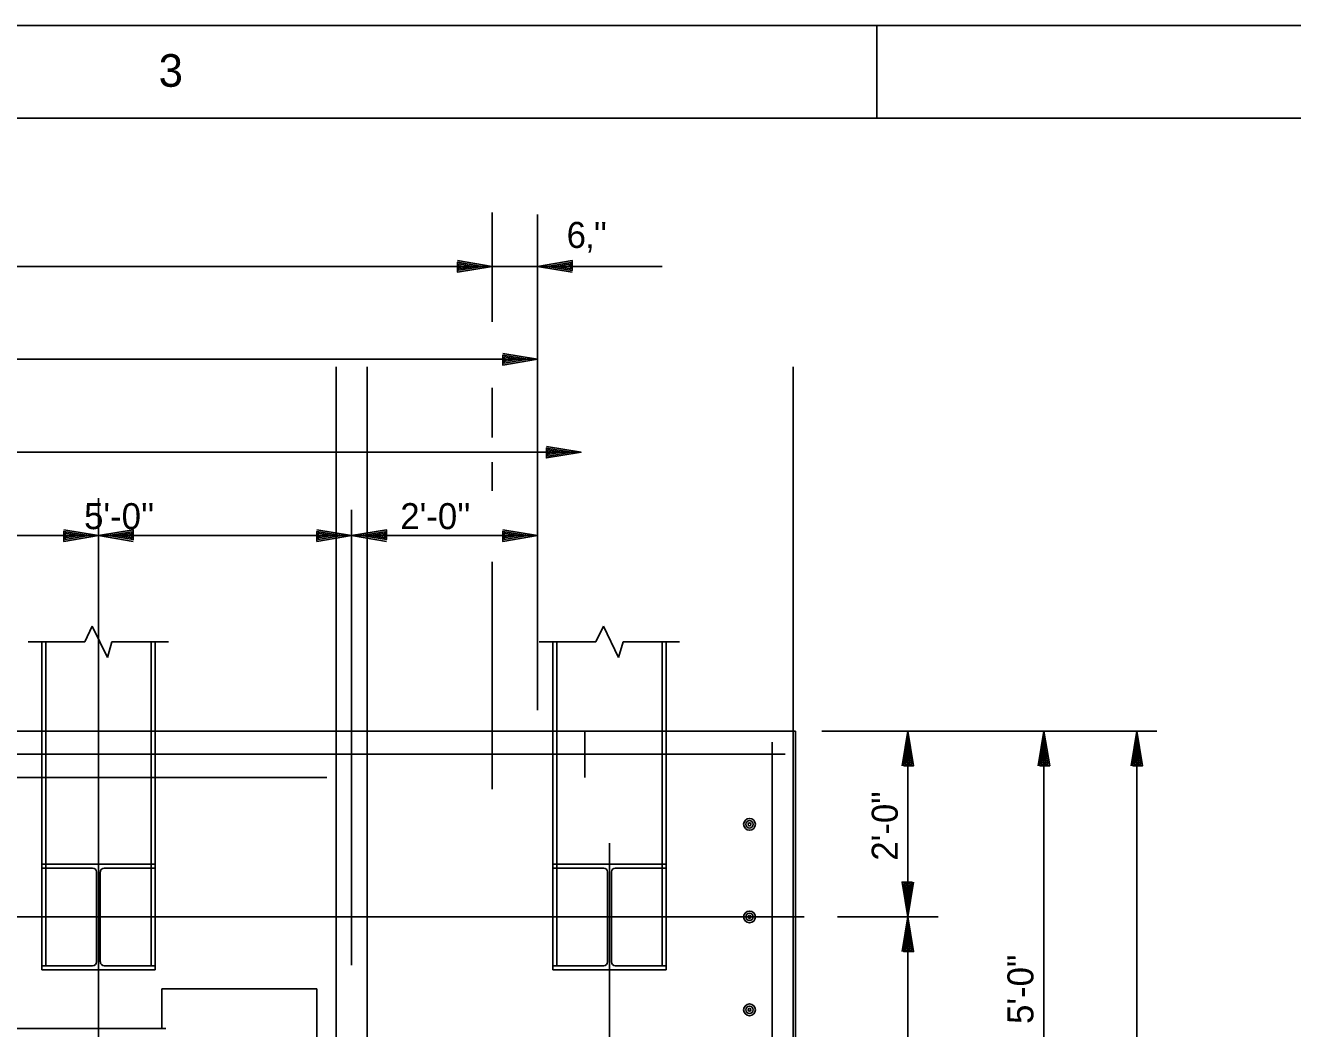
# Model space of a CAD drawing. Extents: x -11983 to -11903, y -13969.5 to -13913.5.
# Drawn here: x -11943.67 to -11930.04, y -13924.28 to -13913.48 of the extents above; entities that cross this region are included whole.
import ezdxf

# ---------------------------------------------------------------- set-up
doc = ezdxf.new("R2010")
doc.units = 0
for name, color, linetype in [('Level 1', 7, 'Continuous'), ('Level 2', 7, 'Continuous'), ('Level 22', 7, 'Continuous'), ('Level 25', 7, 'Continuous'), ('Level 3', 7, 'Continuous'), ('Level 50', 7, 'Continuous'), ('Level 6', 7, 'Continuous')]:
    doc.layers.add(name, color=color, linetype=linetype)

msp = doc.modelspace()

# ---------------------------------------------------------------- linework, layer by layer
at = {"layer": 'Level 1'}
msp.add_line((-11934.512, -13914.481), (-11934.512, -13913.481), dxfattribs=at)
for points in [[(-11983.012, -13913.481), (-11903.012, -13913.481), (-11903.012, -13969.481), (-11983.012, -13969.481)], [(-11980.012, -13914.481), (-11904.012, -13914.481), (-11904.012, -13968.481), (-11980.012, -13968.481)]]:
    msp.add_lwpolyline(points, close=True, dxfattribs=at)
at = {"layer": 'Level 2'}
for p, q in [((-11940.33, -13917.157), (-11940.33, -13932.202)), ((-11939.997, -13917.157), (-11939.997, -13932.202)), ((-11935.413, -13917.157), (-11935.413, -13932.202)), ((-11942.953, -13919.945), (-11943.033, -13920.113)), ((-11942.79, -13920.282), (-11942.953, -13919.945)), ((-11937.453, -13919.945), (-11937.533, -13920.113)), ((-11937.29, -13920.282), (-11937.453, -13919.945)), ((-11943.033, -13920.113), (-11943.643, -13920.113)), ((-11943.497, -13920.113), (-11943.497, -13921.573)), ((-11943.455, -13920.113), (-11943.455, -13921.573)), ((-11942.742, -13920.113), (-11942.79, -13920.282)), ((-11942.134, -13920.113), (-11942.742, -13920.113)), ((-11942.32, -13920.113), (-11942.32, -13921.573)), ((-11942.278, -13920.113), (-11942.278, -13921.573)), ((-11937.533, -13920.113), (-11938.143, -13920.113)), ((-11937.997, -13920.113), (-11937.997, -13921.573)), ((-11937.955, -13920.113), (-11937.955, -13921.573)), ((-11937.242, -13920.113), (-11937.29, -13920.282)), ((-11936.634, -13920.113), (-11937.242, -13920.113)), ((-11936.82, -13920.113), (-11936.82, -13921.573)), ((-11936.778, -13920.113), (-11936.778, -13921.573)), ((-11935.387, -13921.074), (-11957.178, -13921.074)), ((-11937.654, -13921.573), (-11937.654, -13921.074)), ((-11935.387, -13921.074), (-11935.387, -13927.066)), ((-11935.387, -13921.074), (-11935.387, -13929.066)), ((-11940.43, -13921.573), (-11957.178, -13921.573)), ((-11943.497, -13923.6), (-11943.497, -13921.573)), ((-11943.455, -13923.6), (-11943.455, -13921.573)), ((-11942.32, -13923.6), (-11942.32, -13921.573)), ((-11942.278, -13923.6), (-11942.278, -13921.573)), ((-11937.997, -13923.6), (-11937.997, -13921.573)), ((-11937.955, -13923.6), (-11937.955, -13921.573)), ((-11936.82, -13923.6), (-11936.82, -13921.573)), ((-11936.778, -13923.6), (-11936.778, -13921.573)), ((-11942.278, -13922.506), (-11943.497, -13922.506)), ((-11943.497, -13922.548), (-11943.497, -13922.506)), ((-11942.278, -13922.548), (-11942.278, -13922.506)), ((-11936.778, -13922.506), (-11937.997, -13922.506)), ((-11937.997, -13922.548), (-11937.997, -13922.506)), ((-11936.778, -13922.548), (-11936.778, -13922.506)), ((-11942.95, -13922.548), (-11943.497, -13922.548)), ((-11942.908, -13923.558), (-11942.908, -13922.59)), ((-11942.867, -13923.558), (-11942.867, -13922.59)), ((-11942.278, -13922.548), (-11942.825, -13922.548)), ((-11937.45, -13922.548), (-11937.997, -13922.548)), ((-11937.408, -13923.558), (-11937.408, -13922.59)), ((-11937.367, -13923.558), (-11937.367, -13922.59)), ((-11936.778, -13922.548), (-11937.325, -13922.548)), ((-11942.95, -13923.6), (-11943.497, -13923.6)), ((-11943.497, -13923.642), (-11943.497, -13923.6)), ((-11942.278, -13923.6), (-11942.825, -13923.6)), ((-11942.278, -13923.642), (-11942.278, -13923.6)), ((-11937.45, -13923.6), (-11937.997, -13923.6)), ((-11937.997, -13923.642), (-11937.997, -13923.6)), ((-11936.778, -13923.6), (-11937.325, -13923.6)), ((-11936.778, -13923.642), (-11936.778, -13923.6)), ((-11942.278, -13923.642), (-11943.497, -13923.642)), ((-11936.778, -13923.642), (-11937.997, -13923.642)), ((-11940.538, -13923.849), (-11942.205, -13923.849)), ((-11968.183, -13924.274), (-11942.163, -13924.274))]:
    msp.add_line(p, q, dxfattribs=at)
for centre, start, end in [((-11942.95, -13922.59), 0, 90), ((-11942.825, -13922.59), 90, 180), ((-11937.45, -13922.59), 0, 90), ((-11937.325, -13922.59), 90, 180), ((-11942.95, -13923.558), 270, 0), ((-11942.825, -13923.558), 180, 270), ((-11937.45, -13923.558), 270, 0), ((-11937.325, -13923.558), 180, 270)]:
    msp.add_arc(centre, 0.0417, start, end, dxfattribs=at)
at = {"layer": 'Level 22'}
for p, q in [((-11942.887, -13923.074), (-11942.887, -13922.282)), ((-11937.387, -13923.074), (-11937.387, -13922.282)), ((-11942.887, -13924.649), (-11942.887, -13923.074)), ((-11937.387, -13924.649), (-11937.387, -13923.074))]:
    msp.add_line(p, q, dxfattribs=at)
at = {"layer": 'Level 25'}
for p, q in [((-11942.205, -13924.274), (-11942.205, -13923.849)), ((-11940.538, -13926.066), (-11940.538, -13923.849))]:
    msp.add_line(p, q, dxfattribs=at)
at = {"layer": 'Level 3'}
for p, q in [((-11938.65, -13915.496), (-11938.65, -13916.671)), ((-11938.163, -13915.517), (-11938.163, -13920.848)), ((-11938.427, -13916.074), (-11957.178, -13916.074)), ((-11938.65, -13916.074), (-11939.438, -13916.074)), ((-11937.998, -13916.074), (-11938.824, -13916.074)), ((-11938.754, -13916.074), (-11938.754, -13916.074)), ((-11938.65, -13916.074), (-11938.65, -13916.074)), ((-11938.163, -13916.074), (-11938.163, -13916.074)), ((-11938.163, -13916.074), (-11936.82, -13916.074)), ((-11938.059, -13916.074), (-11938.059, -13916.074)), ((-11938.163, -13917.074), (-11957.178, -13917.074)), ((-11938.267, -13917.074), (-11938.267, -13917.074)), ((-11938.163, -13917.074), (-11938.163, -13917.074)), ((-11938.65, -13917.38), (-11938.65, -13917.915)), ((-11937.693, -13918.074), (-11957.178, -13918.074)), ((-11938.65, -13918.182), (-11938.65, -13918.488)), ((-11942.887, -13918.569), (-11942.887, -13919.385)), ((-11942.887, -13918.695), (-11942.887, -13923.074)), ((-11940.163, -13918.695), (-11940.163, -13923.074)), ((-11938.163, -13919.287), (-11938.163, -13918.651)), ((-11950.163, -13918.971), (-11942.887, -13918.971)), ((-11942.887, -13918.971), (-11940.163, -13918.971)), ((-11940.163, -13918.971), (-11938.163, -13918.971)), ((-11938.65, -13919.252), (-11938.65, -13921.699)), ((-11942.887, -13923.594), (-11942.887, -13919.344)), ((-11942.887, -13923.594), (-11942.887, -13919.344)), ((-11942.887, -13923.074), (-11942.887, -13919.344)), ((-11942.887, -13923.074), (-11942.887, -13919.344)), ((-11942.887, -13923.074), (-11942.887, -13919.37)), ((-11940.163, -13923.594), (-11940.163, -13919.344)), ((-11940.163, -13923.074), (-11940.163, -13919.344)), ((-11940.163, -13923.074), (-11940.163, -13919.344)), ((-11940.163, -13923.074), (-11940.163, -13919.37)), ((-11931.499, -13921.074), (-11935.104, -13921.074)), ((-11934.178, -13921.074), (-11934.178, -13923.074)), ((-11934.178, -13921.074), (-11934.178, -13921.074)), ((-11932.713, -13921.074), (-11932.713, -13926.07)), ((-11932.713, -13921.074), (-11932.713, -13921.074)), ((-11931.713, -13921.074), (-11931.713, -13929.066)), ((-11931.713, -13921.074), (-11931.713, -13921.074)), ((-11934.178, -13921.178), (-11934.178, -13921.178)), ((-11932.713, -13921.178), (-11932.713, -13921.178)), ((-11931.713, -13921.178), (-11931.713, -13921.178)), ((-11935.294, -13923.074), (-11950.163, -13923.074)), ((-11933.851, -13923.074), (-11934.934, -13923.074)), ((-11934.178, -13923.074), (-11934.178, -13927.066))]:
    msp.add_line(p, q, dxfattribs=at)
for points in [[(-11939.024, -13916.012), (-11938.65, -13916.074), (-11939.024, -13916.136), (-11939.024, -13916.03), (-11938.754, -13916.074), (-11939.008, -13916.116), (-11939.008, -13916.048), (-11938.854, -13916.074), (-11938.992, -13916.096), (-11938.992, -13916.068), (-11938.958, -13916.074)], [(-11937.789, -13916.136), (-11938.163, -13916.074), (-11937.789, -13916.012), (-11937.789, -13916.118), (-11938.059, -13916.074), (-11937.805, -13916.032), (-11937.805, -13916.1), (-11937.959, -13916.074), (-11937.821, -13916.052), (-11937.821, -13916.08), (-11937.855, -13916.074)], [(-11938.537, -13917.012), (-11938.163, -13917.074), (-11938.537, -13917.136), (-11938.537, -13917.03), (-11938.267, -13917.074), (-11938.521, -13917.116), (-11938.521, -13917.048), (-11938.367, -13917.074), (-11938.505, -13917.096), (-11938.505, -13917.068), (-11938.471, -13917.074)], [(-11934.24, -13921.448), (-11934.178, -13921.074), (-11934.116, -13921.448), (-11934.222, -13921.448), (-11934.178, -13921.178), (-11934.136, -13921.432), (-11934.204, -13921.432), (-11934.178, -13921.278), (-11934.156, -13921.416), (-11934.184, -13921.416), (-11934.178, -13921.382)], [(-11932.775, -13921.448), (-11932.713, -13921.074), (-11932.651, -13921.448), (-11932.757, -13921.448), (-11932.713, -13921.178), (-11932.671, -13921.432), (-11932.739, -13921.432), (-11932.713, -13921.278), (-11932.691, -13921.416), (-11932.719, -13921.416), (-11932.713, -13921.382)], [(-11931.775, -13921.448), (-11931.713, -13921.074), (-11931.651, -13921.448), (-11931.757, -13921.448), (-11931.713, -13921.178), (-11931.671, -13921.432), (-11931.739, -13921.432), (-11931.713, -13921.278), (-11931.691, -13921.416), (-11931.719, -13921.416), (-11931.713, -13921.382)]]:
    msp.add_lwpolyline(points, dxfattribs=at)
at = {"layer": 'Level 50'}
for p, q in [((-11937.797, -13918.074), (-11937.797, -13918.074)), ((-11937.693, -13918.074), (-11937.693, -13918.074)), ((-11942.991, -13918.971), (-11942.991, -13918.971)), ((-11942.887, -13918.971), (-11942.887, -13918.971)), ((-11942.887, -13918.971), (-11942.887, -13918.971)), ((-11942.783, -13918.971), (-11942.783, -13918.971)), ((-11940.267, -13918.971), (-11940.267, -13918.971)), ((-11940.163, -13918.971), (-11940.163, -13918.971)), ((-11940.163, -13918.971), (-11940.163, -13918.971)), ((-11940.059, -13918.971), (-11940.059, -13918.971)), ((-11938.267, -13918.971), (-11938.267, -13918.971)), ((-11938.163, -13918.971), (-11938.163, -13918.971)), ((-11934.178, -13922.97), (-11934.178, -13922.97)), ((-11934.178, -13923.074), (-11934.178, -13923.074)), ((-11934.178, -13923.074), (-11934.178, -13923.074)), ((-11934.178, -13923.178), (-11934.178, -13923.178))]:
    msp.add_line(p, q, dxfattribs=at)
for points in [[(-11938.067, -13918.012), (-11937.693, -13918.074), (-11938.067, -13918.136), (-11938.067, -13918.03), (-11937.797, -13918.074), (-11938.051, -13918.116), (-11938.051, -13918.048), (-11937.897, -13918.074), (-11938.035, -13918.096), (-11938.035, -13918.068), (-11938.001, -13918.074)], [(-11943.261, -13918.909), (-11942.887, -13918.971), (-11943.261, -13919.033), (-11943.261, -13918.927), (-11942.991, -13918.971), (-11943.245, -13919.013), (-11943.245, -13918.945), (-11943.091, -13918.971), (-11943.229, -13918.993), (-11943.229, -13918.965), (-11943.195, -13918.971)], [(-11942.513, -13919.033), (-11942.887, -13918.971), (-11942.513, -13918.909), (-11942.513, -13919.015), (-11942.783, -13918.971), (-11942.529, -13918.929), (-11942.529, -13918.997), (-11942.683, -13918.971), (-11942.545, -13918.949), (-11942.545, -13918.977), (-11942.579, -13918.971)], [(-11940.537, -13918.909), (-11940.163, -13918.971), (-11940.537, -13919.033), (-11940.537, -13918.927), (-11940.267, -13918.971), (-11940.521, -13919.013), (-11940.521, -13918.945), (-11940.367, -13918.971), (-11940.505, -13918.993), (-11940.505, -13918.965), (-11940.471, -13918.971)], [(-11939.789, -13919.033), (-11940.163, -13918.971), (-11939.789, -13918.909), (-11939.789, -13919.015), (-11940.059, -13918.971), (-11939.805, -13918.929), (-11939.805, -13918.997), (-11939.959, -13918.971), (-11939.821, -13918.949), (-11939.821, -13918.977), (-11939.855, -13918.971)], [(-11938.537, -13918.909), (-11938.163, -13918.971), (-11938.537, -13919.033), (-11938.537, -13918.927), (-11938.267, -13918.971), (-11938.521, -13919.013), (-11938.521, -13918.945), (-11938.367, -13918.971), (-11938.505, -13918.993), (-11938.505, -13918.965), (-11938.471, -13918.971)], [(-11934.116, -13922.7), (-11934.178, -13923.074), (-11934.24, -13922.7), (-11934.134, -13922.7), (-11934.178, -13922.97), (-11934.22, -13922.716), (-11934.152, -13922.716), (-11934.178, -13922.87), (-11934.2, -13922.732), (-11934.172, -13922.732), (-11934.178, -13922.766)], [(-11934.24, -13923.448), (-11934.178, -13923.074), (-11934.116, -13923.448), (-11934.222, -13923.448), (-11934.178, -13923.178), (-11934.136, -13923.432), (-11934.204, -13923.432), (-11934.178, -13923.278), (-11934.156, -13923.416), (-11934.184, -13923.416), (-11934.178, -13923.382)]]:
    msp.add_lwpolyline(points, dxfattribs=at)
at = {"layer": 'Level 6'}
for p, q in [((-11935.637, -13921.193), (-11935.637, -13928.927)), ((-11935.499, -13921.324), (-11957.178, -13921.324))]:
    msp.add_line(p, q, dxfattribs=at)
for centre, radius in [((-11935.881, -13922.078), 0.0633), ((-11935.881, -13922.078), 0.0396), ((-11935.881, -13922.078), 0.0158), ((-11935.881, -13923.074), 0.0633), ((-11935.881, -13923.074), 0.0396), ((-11935.881, -13923.074), 0.0158), ((-11935.881, -13924.074), 0.0633), ((-11935.881, -13924.074), 0.0396), ((-11935.881, -13924.074), 0.0158)]:
    msp.add_circle(centre, radius, dxfattribs=at)

# ---------------------------------------------------------------- texts
at = {"layer": 'Level 1'}
msp.add_text('3', height=0.351, dxfattribs=at).set_placement((-11942.239, -13914.142))
at = {"layer": 'Level 3'}
for s, p in [("6‚'' ", (-11937.849, -13915.876)), ("5'-0''", (-11943.042, -13918.902)), ("2'-0''", (-11939.639, -13918.902))]:
    msp.add_text(s, height=0.28, dxfattribs=at).set_placement(p)
for s, p in [('2\'-0"', (-11934.286, -13922.469)), ('5\'-0"', (-11932.826, -13924.226))]:
    msp.add_text(s, height=0.28, rotation=90, dxfattribs=at).set_placement(p)

doc.saveas('drawing.dxf')
